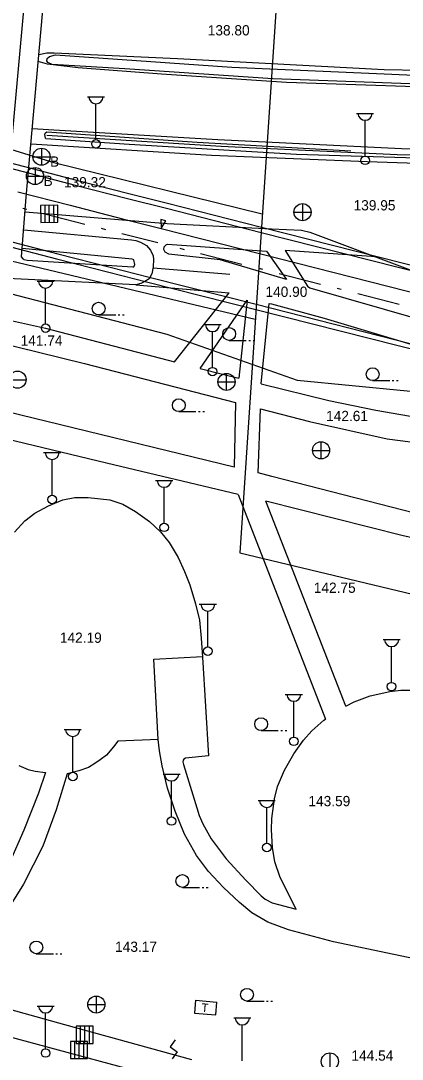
# Model space of a CAD drawing. Extents: x 419101 to 420177, y 4451541 to 4452254.
# Drawn here: x 419367.6 to 419412.3, y 4451893 to 4452014.6 of the extents above; entities that cross this region are included whole.
import ezdxf

# ---------------------------------------------------------------- set-up
doc = ezdxf.new("R2010")
doc.units = 0
for name, color, linetype in [('2_KADASTRO', 7, 'Continuous'), ('3_HALİHAZIR', 7, 'Continuous'), ('Level 53', 7, 'Continuous'), ('Level 60', 7, 'Continuous')]:
    doc.layers.add(name, color=color, linetype=linetype)

msp = doc.modelspace()

# ---------------------------------------------------------------- linework, layer by layer
at = {"layer": '2_KADASTRO'}
msp.add_lwpolyline([(419201.62, 4451892.03), (419189.13, 4451898.23), (419208.25, 4451935.36), (419207.93, 4451941.92), (419215.46, 4451962.72), (419225, 4451987.71), (419233.52, 4452012.36), (419242.83, 4452009.95), (419261.3, 4452004.94), (419280.08, 4452000.79), (419303.08, 4451996.46), (419328.79, 4451991.58), (419337.15, 4451989.99), (419348.32, 4451987.3), (419374.39, 4451980.56), (419384.76, 4451977.88), (419400.02, 4451972.49), (419419.33, 4451970.62), (419421.1, 4451970.45), (419483.51, 4451955.62), (419517.72, 4451947.49)], dxfattribs=at)
at = {"layer": '3_HALİHAZIR'}
for p, q in [((419375.46, 4452005.65), (419377.46, 4452005.65)), ((419376.46, 4452000.65), (419376.46, 4452004.85)), ((419406.98, 4452003.72), (419408.98, 4452003.72)), ((419407.98, 4451998.72), (419407.98, 4452002.91)), ((419370.08, 4451999.64), (419370.08, 4451997.64)), ((419369.08, 4451998.64), (419371.08, 4451998.64)), ((419369.32, 4451997.38), (419369.32, 4451995.38)), ((419368.32, 4451996.38), (419370.32, 4451996.38)), ((419371.98, 4451992.97), (419369.98, 4451992.94)), ((419371.98, 4451992.97), (419369.98, 4451992.94)), ((419371.01, 4451990.95), (419370.98, 4451992.95)), ((419371.56, 4451990.96), (419371.53, 4451992.96)), ((419372.01, 4451990.97), (419371.98, 4451992.97)), ((419372.01, 4451990.97), (419371.98, 4451992.97)), ((419400.67, 4451991.15), (419400.67, 4451993.15)), ((419369.98, 4451992.94), (419370.01, 4451990.94)), ((419369.98, 4451992.94), (419370.01, 4451990.94)), ((419370.51, 4451990.94), (419370.49, 4451992.94)), ((419399.65, 4451992.14), (419401.65, 4451992.14)), ((419370.01, 4451990.94), (419372.01, 4451990.97)), ((419370.01, 4451990.94), (419372.01, 4451990.97)), ((419369.56, 4451984.07), (419371.56, 4451984.07)), ((419370.56, 4451979.07), (419370.56, 4451983.26)), ((419376.77, 4451980.12), (419378.77, 4451980.12)), ((419379.07, 4451980.12), (419379.27, 4451980.12)), ((419379.57, 4451980.12), (419379.77, 4451980.12)), ((419389.11, 4451978.99), (419391.11, 4451978.99)), ((419390.11, 4451973.99), (419390.11, 4451978.18)), ((419392.06, 4451977.15), (419394.06, 4451977.15)), ((419394.36, 4451977.15), (419394.56, 4451977.15)), ((419394.86, 4451977.15), (419395.06, 4451977.15)), ((419366.27, 4451972.53), (419368.27, 4451972.53)), ((419391.76, 4451971.29), (419391.76, 4451973.29)), ((419408.86, 4451972.44), (419410.86, 4451972.44)), ((419411.16, 4451972.44), (419411.36, 4451972.44)), ((419411.66, 4451972.44), (419411.86, 4451972.44)), ((419390.74, 4451972.28), (419392.74, 4451972.28)), ((419386.16, 4451968.81), (419388.16, 4451968.81)), ((419388.46, 4451968.81), (419388.66, 4451968.81)), ((419388.96, 4451968.81), (419389.16, 4451968.81)), ((419402.84, 4451963.28), (419402.84, 4451965.28)), ((419370.33, 4451964.03), (419372.33, 4451964.03)), ((419401.82, 4451964.27), (419403.82, 4451964.27)), ((419371.33, 4451959.03), (419371.33, 4451963.22)), ((419383.45, 4451960.76), (419385.45, 4451960.76)), ((419384.45, 4451955.76), (419384.45, 4451959.95)), ((419388.56, 4451946.28), (419390.56, 4451946.28)), ((419389.56, 4451941.28), (419389.56, 4451945.48)), ((419410.08, 4451942.12), (419412.08, 4451942.12)), ((419411.08, 4451937.12), (419411.08, 4451941.32)), ((419398.63, 4451935.72), (419400.63, 4451935.72)), ((419399.63, 4451930.72), (419399.63, 4451934.92)), ((419372.74, 4451931.6), (419374.74, 4451931.6)), ((419395.8, 4451931.48), (419397.8, 4451931.48)), ((419398.1, 4451931.48), (419398.3, 4451931.48)), ((419398.6, 4451931.48), (419398.8, 4451931.48)), ((419373.74, 4451926.6), (419373.74, 4451930.79)), ((419384.31, 4451926.39), (419386.31, 4451926.39)), ((419385.31, 4451921.39), (419385.31, 4451925.58)), ((419395.46, 4451923.29), (419397.46, 4451923.29)), ((419396.46, 4451918.29), (419396.46, 4451922.48)), ((419386.58, 4451913.12), (419388.58, 4451913.12)), ((419388.88, 4451913.12), (419389.08, 4451913.12)), ((419389.38, 4451913.12), (419389.58, 4451913.12)), ((419369.47, 4451905.35), (419371.47, 4451905.35)), ((419371.77, 4451905.35), (419371.97, 4451905.35)), ((419372.27, 4451905.35), (419372.47, 4451905.35)), ((419375.49, 4451899.4), (419377.49, 4451899.4)), ((419376.51, 4451898.41), (419376.51, 4451900.41)), ((419394.14, 4451899.81), (419396.14, 4451899.81)), ((419396.44, 4451899.81), (419396.64, 4451899.81)), ((419396.94, 4451899.81), (419397.14, 4451899.81)), ((419369.56, 4451899.24), (419371.56, 4451899.24)), ((419370.56, 4451894.24), (419370.56, 4451898.43)), ((419392.59, 4451897.84), (419394.59, 4451897.84)), ((419393.59, 4451892.84), (419393.59, 4451897.03)), ((419376.14, 4451896.87), (419374.14, 4451896.87)), ((419374.14, 4451896.87), (419374.14, 4451894.87)), ((419376.14, 4451896.87), (419374.14, 4451896.87)), ((419374.14, 4451896.87), (419374.14, 4451894.87)), ((419374.64, 4451894.87), (419374.64, 4451896.87)), ((419375.14, 4451894.87), (419375.14, 4451896.87)), ((419375.69, 4451894.87), (419375.69, 4451896.87)), ((419376.14, 4451894.87), (419376.14, 4451896.87)), ((419376.14, 4451894.87), (419376.14, 4451896.87)), ((419375.48, 4451895.09), (419373.48, 4451895.09)), ((419373.48, 4451895.09), (419373.48, 4451893.09)), ((419375.48, 4451895.09), (419373.48, 4451895.09)), ((419373.48, 4451895.09), (419373.48, 4451893.09)), ((419373.98, 4451893.09), (419373.98, 4451895.09)), ((419374.14, 4451894.87), (419376.14, 4451894.87)), ((419374.14, 4451894.87), (419376.14, 4451894.87)), ((419374.48, 4451893.09), (419374.48, 4451895.09)), ((419375.03, 4451893.09), (419375.03, 4451895.09)), ((419375.48, 4451893.09), (419375.48, 4451895.09)), ((419375.48, 4451893.09), (419375.48, 4451895.09)), ((419403.87, 4451891.75), (419403.87, 4451893.75)), ((419373.48, 4451893.09), (419375.48, 4451893.09)), ((419373.48, 4451893.09), (419375.48, 4451893.09))]:
    msp.add_line(p, q, dxfattribs=at)
for points in [[(419381.11, 4451983.64), (419366.12, 4451984.4), (419365.57, 4451984.71), (419365.42, 4451985.09), (419366.29, 4451996.93), (419369.67, 4452034.29), (419370.05, 4452035.01), (419370.59, 4452035.4), (419371.31, 4452035.73), (419371.63, 4452035.78), (419387.45, 4452034.11), (419387.88, 4452034.01), (419388.5, 4452033.68), (419388.96, 4452033.23), (419389.22, 4452032.59), (419389.4, 4452031.61), (419389.33, 4452030.87), (419389.05, 4452030.24), (419388.58, 4452029.64), (419387.95, 4452029.14), (419387.21, 4452028.85)], [(419380.78, 4451985.73), (419368.41, 4451986.49), (419368.05, 4451986.59), (419367.96, 4451986.64), (419367.75, 4451986.93), (419368.3, 4451993.91), (419370.55, 4452019.33), (419371.65, 4452032.88), (419371.79, 4452033.22), (419372.03, 4452033.36), (419386.63, 4452032.03), (419386.92, 4452031.91), (419387.02, 4452031.72), (419387, 4452031.41), (419386.89, 4452031.28), (419386.74, 4452031.17)], [(419369.78, 4452010.61), (419370.7, 4452010.79), (419371.57, 4452010.8), (419385.99, 4452010.14), (419410.23, 4452008.84), (419435.75, 4452008.37), (419455.47, 4452008.38), (419471.68, 4452008.93), (419489.79, 4452009.85), (419506.52, 4452010.95), (419523.39, 4452012.32)], [(419523.56, 4452010.66), (419498.7, 4452008.67), (419481.5, 4452007.62), (419467.56, 4452007.09), (419453.42, 4452006.64), (419434.69, 4452006.58), (419417.53, 4452007.01), (419397.17, 4452007.76), (419379.85, 4452008.94), (419371.31, 4452009.42), (419370.84, 4452009.66), (419370.72, 4452009.88), (419370.75, 4452010.12), (419371, 4452010.38), (419371.71, 4452010.58), (419392.39, 4452009.14), (419420.02, 4452007.92), (419440.12, 4452007.55), (419459.43, 4452007.84), (419481.56, 4452008.61), (419500.31, 4452009.72), (419523.47, 4452011.5)], [(419523.57, 4452010.48), (419506.77, 4452009.12), (419495.3, 4452008.36), (419480.23, 4452007.32), (419463.36, 4452006.81), (419450.22, 4452006.42), (419435.54, 4452006.49), (419417.36, 4452006.69), (419398.79, 4452007.33), (419384.13, 4452008.3), (419374.37, 4452009.03), (419370.78, 4452009.48), (419369.7, 4452009.78)], [(419369.01, 4452001.93), (419371.54, 4452001.78), (419390.75, 4452000.64), (419412.25, 4451999.61), (419421.5, 4451999.55), (419436.25, 4451999.32), (419446.62, 4451999.39), (419458.4, 4451999.48), (419473.15, 4451999.65), (419489.8, 4452000.45), (419506.65, 4452001.38), (419524.3, 4452003.01)], [(419524.4, 4452002.04), (419511.23, 4452000.86), (419489.66, 4451999.46), (419471.43, 4451998.67), (419456.35, 4451998.29), (419441.48, 4451998.06), (419420.44, 4451998.27), (419399.94, 4451998.92), (419380.33, 4452000.09), (419370.6, 4452000.73), (419370.56, 4452000.8), (419370.46, 4452001.23), (419370.51, 4452001.41), (419370.69, 4452001.54)], [(419370.69, 4452001.54), (419388.33, 4452000.36), (419406.31, 4451999.34)], [(419370.72, 4452001.18), (419391.14, 4451999.86), (419411.74, 4451998.91), (419430.81, 4451998.51), (419445.08, 4451998.35), (419459.49, 4451998.66), (419483.09, 4451999.38), (419502.55, 4452000.63), (419515.97, 4452001.69), (419524.35, 4452002.5)], [(419520.23, 4451996.53), (419517.86, 4451996.01), (419515.99, 4451995.82), (419506.36, 4451996.21), (419494.21, 4451996.78), (419485.31, 4451997.01), (419477.85, 4451997.26), (419471.6, 4451997.42), (419461.62, 4451997.37), (419445.71, 4451997.39), (419430.5, 4451997.29), (419408.21, 4451998.06), (419390, 4451998.8), (419368.85, 4452000.12)], [(419368.17, 4451992.18), (419384.8, 4451990.82), (419397.02, 4451990.21), (419400.54, 4451990.04), (419401.5, 4451989.81), (419412.93, 4451985.54), (419430.95, 4451978.9)], [(419296.14, 4451985.88), (419309.25, 4451982.8), (419310.12, 4451984.9), (419311.03, 4451986.26), (419312.23, 4451987.59), (419313.42, 4451988.39), (419315.4, 4451989.18), (419317.77, 4451989.8), (419319.32, 4451989.97), (419320.54, 4451989.98), (419340.86, 4451985.02), (419351.18, 4451982.86), (419370.56, 4451978.57), (419385.64, 4451974.65)], [(419368, 4451990.08), (419380.61, 4451988.93), (419381.12, 4451988.85), (419381.66, 4451988.65), (419382.36, 4451988.25), (419382.85, 4451987.72), (419383.15, 4451987.03), (419383.21, 4451986.61), (419383.17, 4451985.77), (419383.02, 4451984.95), (419382.69, 4451984.36), (419382.19, 4451984.03), (419381.73, 4451983.82), (419381.11, 4451983.64)], [(419392.65, 4451962.31), (419376.96, 4451966.13), (419353.52, 4451971.81), (419313.74, 4451981.52), (419312.26, 4451982.09), (419312.91, 4451983.8), (419313.51, 4451984.97), (419314.04, 4451985.56), (419314.61, 4451985.97), (419315.29, 4451986.19), (419318.23, 4451987.02), (419319.2, 4451987.19), (419319.85, 4451987.19), (419336.84, 4451983.12), (419361.78, 4451977.72), (419375.12, 4451974.46), (419392.79, 4451969.89)], [(419380.78, 4451985.73), (419380.95, 4451985.85), (419381.01, 4451986.02), (419380.9, 4451986.59), (419380.71, 4451986.64), (419367.83, 4451987.91)], [(419409.26, 4451986.91), (419398.61, 4451987.65), (419401.25, 4451983.49), (419401.52, 4451983.3), (419414.43, 4451979.6), (419441.71, 4451971.64), (419442.67, 4451974.75)], [(419383.14, 4451985.63), (419392.13, 4451984.91)], [(419381.11, 4451983.64), (419392.06, 4451982.72)], [(419385.64, 4451974.65), (419392.06, 4451982.72)], [(419388.68, 4451973.86), (419394.17, 4451981.86), (419393.21, 4451972.71)], [(419395.81, 4451972.08), (419396.74, 4451981.47)], [(419396.74, 4451981.47), (419397.02, 4451981.42), (419403.19, 4451979.75), (419416.44, 4451975.78), (419437.13, 4451969.8)], [(419388.68, 4451973.86), (419391.27, 4451973.19), (419393.21, 4451972.71)], [(419395.81, 4451972.08), (419403.74, 4451970.13), (419409.25, 4451968.97), (419415.1, 4451967.98), (419420.11, 4451967.31), (419422.55, 4451967.17), (419425.7, 4451967.4), (419430.75, 4451968.21), (419434.67, 4451969.12), (419437.13, 4451969.8)], [(419392.79, 4451969.89), (419392.65, 4451962.31)], [(419395.45, 4451961.63), (419395.72, 4451969.13)], [(419395.72, 4451969.13), (419401.48, 4451967.65), (419410.55, 4451965.61), (419416.92, 4451964.79), (419421.35, 4451964.47), (419425.19, 4451964.55), (419432.07, 4451965.21), (419432.72, 4451965.21), (419432.76, 4451965.2)], [(419393.13, 4451959.12), (419377.69, 4451962.78), (419363.89, 4451966.08)], [(419429.47, 4451953.49), (419416.65, 4451956.19), (419397.06, 4451961.23), (419395.45, 4451961.63)], [(419393.13, 4451959.12), (419403.34, 4451932.83)], [(419366.92, 4451954.72), (419368.13, 4451956.01), (419369.3, 4451956.92), (419370.89, 4451957.77), (419372.59, 4451958.47), (419373.98, 4451958.74), (419375.56, 4451958.74), (419378.07, 4451958.5), (419379.6, 4451957.99), (419381.08, 4451957.12), (419382.71, 4451955.96), (419384.03, 4451954.75), (419385.03, 4451953.48), (419386.07, 4451951.75), (419386.83, 4451950.08), (419387.44, 4451948.54), (419388.11, 4451946.33), (419388.57, 4451944.39), (419388.79, 4451942.3), (419388.95, 4451940.09), (419389.63, 4451928.51), (419386.96, 4451928.25), (419386.76, 4451928.14), (419386.67, 4451928.01), (419386.64, 4451927.83), (419386.72, 4451927.49), (419388.27, 4451922.42), (419388.56, 4451921.54), (419388.96, 4451920.55), (419389.94, 4451918.81), (419391.7, 4451916.45), (419394.02, 4451913.99), (419395.8, 4451912.12), (419396.29, 4451911.73), (419397.11, 4451911.33), (419399.91, 4451910.59), (419398.03, 4451914.29), (419397.41, 4451916.13), (419397.14, 4451917.78), (419397, 4451919.88), (419397.06, 4451921.18), (419397.35, 4451923.48), (419397.72, 4451924.93), (419398.52, 4451926.83), (419399.65, 4451928.74), (419400.77, 4451930.34), (419401.74, 4451931.46), (419403.15, 4451932.69), (419403.34, 4451932.83)], [(419405.72, 4451934.34), (419406.69, 4451934.85), (419408.58, 4451935.54), (419410.87, 4451936.07), (419412.16, 4451936.2), (419413.48, 4451936.21), (419415.47, 4451936.14), (419416.48, 4451935.95), (419425.37, 4451934.29), (419428.79, 4451950.69), (419412.45, 4451954.29), (419396.35, 4451958.32)], [(419405.72, 4451934.34), (419396.35, 4451958.32)], [(419383.76, 4451930.44), (419383.23, 4451939.82), (419388.95, 4451940.14)], [(419418.43, 4451903.77), (419404.27, 4451906.76), (419398.99, 4451908.15), (419396.6, 4451909.07), (419394.73, 4451910.14), (419393.27, 4451911.34), (419391.38, 4451913.1), (419389.62, 4451914.97), (419388.22, 4451916.84), (419386.82, 4451919.37), (419385.75, 4451922.06), (419384.84, 4451924.73), (419384.2, 4451927.37), (419383.9, 4451929.12), (419383.76, 4451930.44), (419379.01, 4451930.23), (419378.52, 4451929.58), (419377.69, 4451928.62), (419376.94, 4451928.06), (419376.32, 4451927.61), (419375.57, 4451927.14), (419374.46, 4451926.77), (419373.09, 4451926.43), (419371.81, 4451922.2), (419370.23, 4451917.94), (419367.96, 4451913.51), (419365.71, 4451909.87)], [(419367.41, 4451927.4), (419368.51, 4451926.91), (419369.33, 4451926.72), (419370.53, 4451926.58), (419369.71, 4451924.16), (419368.02, 4451919.82), (419366.32, 4451915.99)], [(419408.05, 4451853.42), (419408.36, 4451853.43), (419408.59, 4451853.49), (419408.87, 4451853.88), (419412.4, 4451868.2), (419415.44, 4451880.8), (419415.54, 4451882.03), (419415.38, 4451882.66), (419414.99, 4451883.08), (419398.26, 4451887.05), (419388.86, 4451889.55), (419363.65, 4451896.34), (419342.32, 4451901.92), (419311.08, 4451910.25), (419292.54, 4451915.37), (419291.92, 4451915.51), (419290.05, 4451906.62), (419289.16, 4451901.92), (419288.75, 4451899.4), (419288.63, 4451898.19)], [(419358.16, 4451901.14), (419372.78, 4451897.08), (419387.65, 4451893)], [(419388.13, 4451899.91), (419388.01, 4451898.41)], [(419388.13, 4451899.91), (419390.62, 4451899.71)], [(419390.5, 4451898.22), (419390.62, 4451899.71)], [(419388.01, 4451898.41), (419390.5, 4451898.22)], [(419385.75, 4451895.28), (419385.16, 4451894.47), (419385.97, 4451893.88), (419385.39, 4451893.07)]]:
    msp.add_lwpolyline(points, dxfattribs=at)
msp.add_lwpolyline([(419384.83, 4451988.4), (419396.42, 4451987.57), (419398.77, 4451984.29), (419390.99, 4451986.59), (419384.98, 4451987.25), (419384.58, 4451987.49), (419384.41, 4451987.79), (419384.46, 4451988.08), (419384.7, 4451988.36)], close=True, dxfattribs=at)
for centre, radius in [((419376.46, 4452000.15), 0.5), ((419370.08, 4451998.64), 1), ((419407.98, 4451998.22), 0.5), ((419369.32, 4451996.38), 1), ((419400.65, 4451992.15), 1), ((419376.77, 4451980.87), 0.75), ((419370.56, 4451978.57), 0.5), ((419392.06, 4451977.9), 0.75), ((419367.27, 4451972.55), 1), ((419390.11, 4451973.49), 0.5), ((419408.86, 4451973.19), 0.75), ((419391.75, 4451972.29), 1), ((419386.16, 4451969.56), 0.75), ((419402.82, 4451964.28), 1), ((419371.33, 4451958.53), 0.5), ((419384.45, 4451955.26), 0.5), ((419389.56, 4451940.78), 0.5), ((419411.08, 4451936.62), 0.5), ((419395.8, 4451932.23), 0.75), ((419399.63, 4451930.22), 0.5), ((419373.74, 4451926.1), 0.5), ((419385.31, 4451920.89), 0.5), ((419396.46, 4451917.79), 0.5), ((419386.58, 4451913.87), 0.75), ((419369.47, 4451906.1), 0.75), ((419394.14, 4451900.56), 0.75), ((419376.5, 4451899.41), 1), ((419370.56, 4451893.74), 0.5), ((419403.85, 4451892.76), 1)]:
    msp.add_circle(centre, radius, dxfattribs=at)
for centre in [(419376.46, 4452005.68), (419407.98, 4452003.75), (419370.56, 4451984.1), (419390.11, 4451979.02), (419371.33, 4451964.06), (419384.45, 4451960.79), (419389.56, 4451946.31), (419411.08, 4451942.15), (419399.63, 4451935.75), (419373.74, 4451931.63), (419385.31, 4451926.42), (419396.46, 4451923.32), (419370.56, 4451899.27), (419393.59, 4451897.87)]:
    msp.add_arc(centre, 0.837, 183.298, 356.9072, dxfattribs=at)
at = {"layer": 'Level 53'}
for p, q in [((419361.97, 4451999.08), (419368.07, 4451997.49)), ((419361.82, 4451998.5), (419367.92, 4451996.9)), ((419367.92, 4451996.9), (419374.03, 4451995.33)), ((419368.07, 4451997.49), (419374.18, 4451995.91)), ((419374.18, 4451995.91), (419380.3, 4451994.35)), ((419367.3, 4451994.53), (419373.42, 4451992.96)), ((419374.03, 4451995.33), (419380.15, 4451993.77)), ((419380.3, 4451994.35), (419384.85, 4451993.19)), ((419373.42, 4451992.96), (419379.55, 4451991.39)), ((419380.15, 4451993.77), (419384.7, 4451992.61)), ((419384.85, 4451993.19), (419395.84, 4451990.4)), ((419367.88, 4451992.63), (419368.36, 4451992.5)), ((419370.3, 4451992), (419375.14, 4451990.76)), ((419384.7, 4451992.61), (419395.8, 4451989.79)), ((419379.55, 4451991.39), (419384.1, 4451990.24)), ((419384.64, 4451991.13), (419384.05, 4451991.28)), ((419384.05, 4451991.28), (419384.1, 4451990.24)), ((419384.1, 4451990.24), (419384.64, 4451991.13)), ((419377.08, 4451990.27), (419377.56, 4451990.14)), ((419379.5, 4451989.65), (419383.69, 4451988.59)), ((419384.1, 4451990.24), (419395.63, 4451987.31)), ((419395.8, 4451989.79), (419562.82, 4451947.36)), ((419395.84, 4451990.4), (419395.84, 4451990.4)), ((419395.84, 4451990.4), (419562.96, 4451947.94)), ((419365.7, 4451988.29), (419371.84, 4451986.71)), ((419365.85, 4451988.87), (419371.98, 4451987.29)), ((419371.98, 4451987.29), (419378.12, 4451985.72)), ((419386.28, 4451987.93), (419386.77, 4451987.8)), ((419388.71, 4451987.31), (419393.55, 4451986.08)), ((419395.63, 4451987.31), (419562.21, 4451944.99)), ((419371.84, 4451986.71), (419377.97, 4451985.14)), ((419378.12, 4451985.72), (419382.68, 4451984.56)), ((419377.97, 4451985.14), (419382.54, 4451983.98)), ((419382.68, 4451984.56), (419395.24, 4451981.37)), ((419395.49, 4451985.59), (419395.52, 4451985.58)), ((419395.52, 4451985.58), (419395.52, 4451985.58)), ((419395.52, 4451985.58), (419395.98, 4451985.47)), ((419397.91, 4451984.97), (419402.76, 4451983.74)), ((419382.54, 4451983.98), (419395.2, 4451980.76)), ((419404.7, 4451983.25), (419405.18, 4451983.13)), ((419407.12, 4451982.63), (419411.97, 4451981.4)), ((419395.24, 4451981.37), (419456.82, 4451965.73)), ((419395.2, 4451980.76), (419456.67, 4451965.14))]:
    msp.add_line(p, q, dxfattribs=at)
at = {"layer": 'Level 60'}
for points in [[(419688.99, 4452017.19), (419689.04, 4452022.57), (419759.95, 4452036.2), (419762.43, 4452036.82), (419753.76, 4452095.96), (419557.74, 4452048.27), (419399.19, 4452040.84), (419393.3, 4451952.28), (419552.47, 4451914.19), (419541.95, 4451850.4), (419587.29, 4451839.81)], [(419395.12, 4451979.59), (419343.13, 4451991.99), (419309.64, 4452002.88), (419261.62, 4452018.86), (419209.72, 4452039.75), (419217.47, 4452053.79), (419279.81, 4452027.21), (419306.51, 4452017.96), (419371.54, 4451997.96), (419395.94, 4451991.97)]]:
    msp.add_lwpolyline(points, dxfattribs=at)

# ---------------------------------------------------------------- texts
at = {"layer": '3_HALİHAZIR'}
for s, height, rotation, p in [('138.80 ', 1.2, 359.998, (419389.55, 4452012.84)), ('139.32 ', 1.2, 359.998, (419372.71, 4451995.06)), ('139.95 ', 1.2, 359.998, (419406.63, 4451992.36)), ('140.90 ', 1.2, 359.998, (419396.31, 4451982.24)), ('141.74 ', 1.2, 359.998, (419367.63, 4451976.53)), ('142.61 ', 1.2, 359.998, (419403.41, 4451967.7)), ('142.75 ', 1.2, 359.998, (419401.97, 4451947.6)), ('142.19 ', 1.2, 359.998, (419372.23, 4451941.75)), ('143.59 ', 1.2, 359.998, (419401.34, 4451922.63)), ('143.17 ', 1.2, 359.998, (419378.7, 4451905.58)), ('T', 1, 355.4423, (419388.77, 4451898.57)), ('144.54 ', 1.2, 359.998, (419406.38, 4451892.84))]:
    msp.add_text(s, height=height, rotation=rotation, dxfattribs=at).set_placement(p)
for p in [(419371.08, 4451997.48), (419370.32, 4451995.22)]:
    msp.add_text('B', height=1.2, dxfattribs=at).set_placement(p)

doc.saveas('drawing.dxf')
